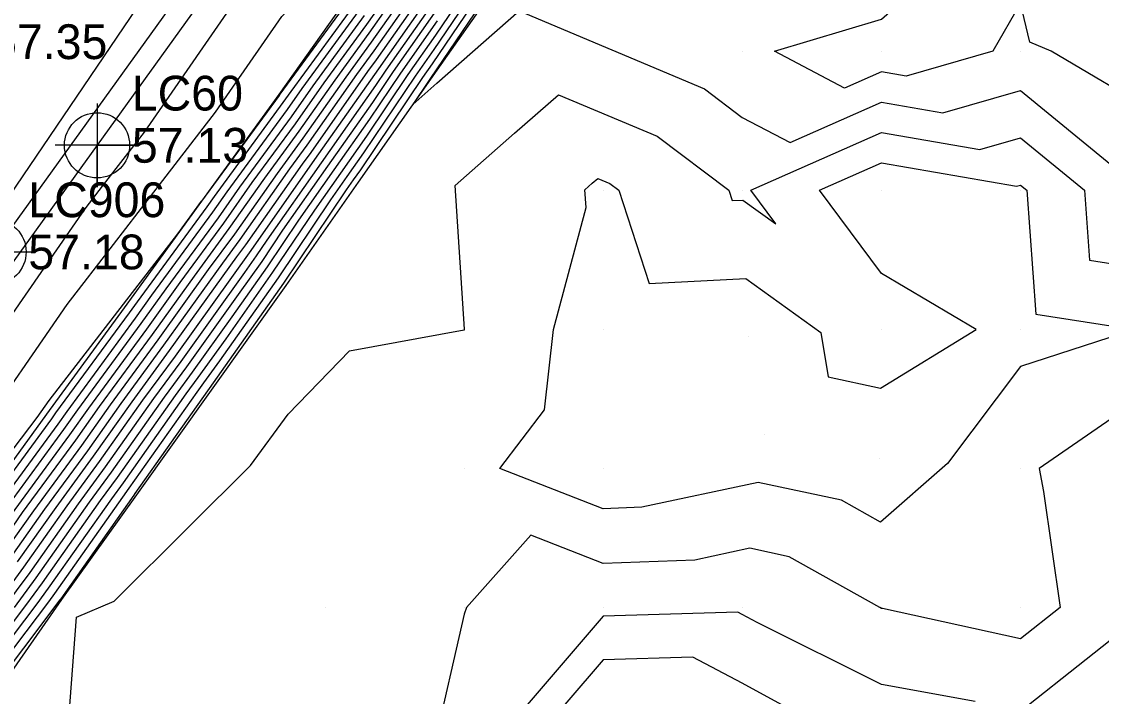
# Model space of a CAD drawing. Extents: x 2188792 to 2191981, y 386090 to 389710.
# Drawn here: x 2189698.4 to 2189776.1, y 386953.7 to 387002.3 of the extents above; entities that cross this region are included whole.
import ezdxf

# ---------------------------------------------------------------- set-up
doc = ezdxf.new("R2010")
doc.units = 0
for name, color, linetype in [('DTM Contours Major', 7, 'Continuous'), ('DTM Contours Minor', 7, 'Continuous'), ('Exist DTM QL2 LIDAR Elevation Point', 7, 'Continuous'), ('Exist Roads EOP', 7, 'Continuous'), ('Exist Roads EOP Cogo Elevation', 7, 'Continuous'), ('Exist Roads EOP Cogo Number', 7, 'Continuous'), ('Exist Roads EOP Cogo Point CELL', 7, 'Continuous'), ('Exist Roads EOT', 7, 'Continuous'), ('Exist Roads EOT Cogo Elevation', 7, 'Continuous'), ('Exist Roads EOT Cogo Number', 7, 'Continuous'), ('Exist Roads EOT Cogo Point CELL', 7, 'Continuous'), ('PH Exist DTM Breakline', 7, 'Continuous')]:
    doc.layers.add(name, color=color, linetype=linetype)

msp = doc.modelspace()

# ---------------------------------------------------------------- linework, layer by layer
at = {"layer": 'DTM Contours Major'}
for points in [[(2189690.321, 386970.473), (2189702.993, 386988.788), (2189704.322, 386990.511), (2189705.738, 386992.346), (2189707.249, 386994.304), (2189717.366, 387008.941), (2189718.756, 387010.444), (2189720.618, 387012.458), (2189723.242, 387015.296), (2189734.595, 387032.184), (2189736.495, 387033.703), (2189737.964, 387036.279), (2189739.21, 387038.462), (2189748.491, 387050.734), (2189750.059, 387053.337), (2189751.431, 387055.614), (2189750.977, 387056.76), (2189764.817, 387076.56)], [(2189731.016, 387005.466), (2189728.189, 387001.282), (2189726.193, 386998.439), (2189723.215, 386994.023), (2189721.346, 386991.363), (2189719.478, 386988.703), (2189716.473, 386984.23), (2189713.098, 386979.449), (2189711.094, 386976.657), (2189710.235, 386975.488), (2189705.717, 386969.084), (2189704.88, 386967.945), (2189700.342, 386961.512), (2189699.528, 386960.404), (2189694.991, 386954.414)], [(2189728.008, 387005.341), (2189723.907, 386999.502), (2189723.293, 386998.66), (2189719.209, 386992.844), (2189718.589, 386992), (2189714.51, 386986.192), (2189713.883, 386985.338), (2189709.045, 386978.598), (2189706.341, 386974.916), (2189703.581, 386971.003), (2189700.877, 386967.324), (2189698.116, 386963.409)], [(2189723.055, 387002.687), (2189719.368, 386997.637), (2189717.801, 386995.406), (2189714.085, 386990.343), (2189712.547, 386988.153), (2189708.788, 386983.034), (2189706.996, 386980.538), (2189702.447, 386974.345), (2189701.444, 386972.923), (2189696.874, 386966.702)]]:
    msp.add_lwpolyline(points, dxfattribs=at)
at = {"layer": 'DTM Contours Minor'}
for points in [[(2189809.4, 387152.406), (2189801.396, 387139.864), (2189794.846, 387131.758), (2189788.146, 387120.877), (2189781.876, 387111.472), (2189771.155, 387095.136), (2189767.896, 387090.241), (2189758.451, 387075.833), (2189755.214, 387070.994), (2189740.876, 387051.783), (2189738.057, 387047.608), (2189727.447, 387033.342), (2189723.289, 387027.488), (2189710.113, 387008.133), (2189707.688, 387004.715), (2189696.068, 386987.603)], [(2189694.937, 386972.126), (2189701.702, 386981.904), (2189705.036, 386986.223), (2189708.586, 386990.823), (2189712.374, 386995.732), (2189717.133, 387002.617), (2189721.107, 387006.915), (2189726.432, 387012.673), (2189732.935, 387019.706), (2189733.562, 387020.567), (2189733.582, 387020.591), (2189739.089, 387028.13), (2189739.289, 387028.377), (2189743.879, 387035.174), (2189744.039, 387035.369), (2189748.66, 387042.228), (2189748.771, 387042.362), (2189753.429, 387049.296), (2189753.48, 387049.355), (2189756.636, 387054.069), (2189757.992, 387056.32), (2189756.554, 387059.949)], [(2189770.901, 387000.78), (2189770.242, 387003.583), (2189768.255, 387000.121), (2189762.025, 386998.338), (2189760.241, 386998.646), (2189757.594, 386997.473), (2189752.556, 387000.121), (2189760.241, 387002.416), (2189769.018, 387010.122), (2189767.681, 387017.562), (2189767.664, 387020.123), (2189770.242, 387023.147), (2189772.595, 387022.475), (2189780.243, 387023.562)], [(2189731.604, 387005.483), (2189728.07, 387000.253), (2189726.722, 386998.332), (2189722.999, 386992.813), (2189721.81, 386991.121), (2189720.622, 386989.428), (2189716.865, 386983.838), (2189712.647, 386977.862), (2189711.504, 386976.269), (2189711.014, 386975.602), (2189706.144, 386968.701), (2189705.681, 386968.07), (2189700.788, 386961.133), (2189700.351, 386960.539), (2189695.456, 386954.076)], [(2189732.192, 387005.5), (2189727.951, 386999.224), (2189727.251, 386998.226), (2189722.783, 386991.602), (2189722.274, 386990.878), (2189721.766, 386990.154), (2189717.258, 386983.446), (2189712.195, 386976.274), (2189711.913, 386975.881), (2189711.792, 386975.716), (2189706.572, 386968.317), (2189706.482, 386968.194), (2189701.233, 386960.753), (2189701.174, 386960.674), (2189695.921, 386953.739)], [(2189728.665, 387005.397), (2189724.078, 386998.864), (2189719.49, 386992.332), (2189714.902, 386985.799), (2189709.455, 386978.209), (2189707.12, 386975.03), (2189704.008, 386970.62), (2189701.678, 386967.448), (2189698.562, 386963.03), (2189696.236, 386959.866)], [(2189726.035, 387005.172), (2189723.396, 387001.413), (2189720.938, 386998.046), (2189718.364, 386994.381), (2189715.887, 386991.006), (2189713.332, 386987.368), (2189710.826, 386983.956), (2189707.816, 386979.762), (2189704.005, 386974.573), (2189702.299, 386972.155), (2189698.475, 386966.951), (2189696.781, 386964.548)], [(2189726.693, 387005.228), (2189723.566, 387000.776), (2189721.723, 386998.251), (2189718.646, 386993.869), (2189716.787, 386991.337), (2189713.724, 386986.976), (2189711.845, 386984.417), (2189708.226, 386979.374), (2189704.784, 386974.688), (2189702.726, 386971.771), (2189699.276, 386967.075), (2189697.226, 386964.168)], [(2189727.35, 387005.284), (2189723.737, 387000.139), (2189722.508, 386998.455), (2189718.927, 386993.357), (2189717.688, 386991.669), (2189714.117, 386986.584), (2189712.864, 386984.878), (2189708.635, 386978.986), (2189705.562, 386974.802), (2189703.153, 386971.387), (2189700.077, 386967.199), (2189697.671, 386963.789)], [(2189725.378, 387005.115), (2189723.225, 387002.05), (2189720.153, 386997.842), (2189718.083, 386994.894), (2189714.986, 386990.675), (2189712.939, 386987.761), (2189709.807, 386983.495), (2189707.406, 386980.15), (2189703.226, 386974.459), (2189701.871, 386972.539), (2189697.675, 386966.826)], [(2189732.78, 387005.517), (2189727.833, 386998.195), (2189727.779, 386998.119), (2189726.547, 386996.292), (2189728.28, 386997.816), (2189734.197, 387003.02), (2189747.529, 386997.409), (2189750.24, 386995.358), (2189753.674, 386993.554), (2189760.241, 386996.463), (2189764.665, 386995.697), (2189770.242, 386997.294), (2189778.993, 386990.12)], [(2189694.035, 386966.557), (2189699.554, 386973.778), (2189700.412, 386975.019), (2189705.749, 386981.935), (2189709.658, 386987), (2189711.369, 386989.33), (2189711.382, 386989.349), (2189716.957, 386996.943), (2189717.013, 386997.024), (2189722.543, 387004.599)], [(2189728.546, 387004.368), (2189724.606, 386998.758), (2189723.862, 386997.654), (2189719.954, 386992.09), (2189716.046, 386986.525), (2189715.295, 386985.407), (2189714.451, 386984.212), (2189709.865, 386977.821), (2189707.899, 386975.145), (2189704.435, 386970.236), (2189702.479, 386967.572), (2189699.007, 386962.651), (2189697.059, 386960)], [(2189695.273, 386966.453), (2189700.59, 386973.69), (2189700.89, 386974.116), (2189706.177, 386981.314), (2189706.75, 386982.113), (2189711.761, 386988.937), (2189712.283, 386989.68), (2189717.239, 386996.431), (2189717.798, 386997.228), (2189722.714, 387003.962)], [(2189722.884, 387003.325), (2189718.583, 386997.433), (2189717.52, 386995.919), (2189713.184, 386990.012), (2189712.154, 386988.545), (2189707.769, 386982.573), (2189706.587, 386980.926), (2189701.669, 386974.23), (2189701.017, 386973.306), (2189696.074, 386966.577)], [(2189728.427, 387003.339), (2189725.135, 386998.652), (2189723.646, 386996.444), (2189720.418, 386991.847), (2189717.19, 386987.251), (2189715.688, 386985.015), (2189714, 386982.624), (2189710.274, 386977.433), (2189708.677, 386975.259), (2189704.862, 386969.852), (2189703.279, 386967.697), (2189699.452, 386962.271), (2189697.882, 386960.135)], [(2189728.308, 387002.31), (2189725.664, 386998.545), (2189723.43, 386995.233), (2189720.882, 386991.605), (2189718.334, 386987.977), (2189716.08, 386984.623), (2189713.549, 386981.037), (2189710.684, 386977.045), (2189709.456, 386975.373), (2189705.29, 386969.468), (2189704.08, 386967.821), (2189699.897, 386961.892), (2189698.705, 386960.27), (2189694.526, 386954.752)], [(2189780.243, 386995.53), (2189772.447, 387000.121), (2189770.901, 387000.78)], [(2189701.814, 386952.133), (2189702.366, 386959.444), (2189705.083, 386960.579), (2189710.475, 386965.953), (2189714.881, 386970.344), (2189717.599, 386974.034), (2189721.997, 386978.583), (2189730.239, 386980.079), (2189730.256, 386980.102), (2189730.258, 386980.119), (2189730.264, 386980.145), (2189729.598, 386990.469), (2189733.866, 386994.222), (2189737.019, 386996.995), (2189744.124, 386994.005), (2189749.26, 386990.12), (2189749.502, 386989.382), (2189750.269, 386989.421), (2189752.652, 386987.708), (2189750.851, 386990.12), (2189760.241, 386994.28), (2189767.305, 386993.057), (2189770.242, 386993.898), (2189774.851, 386990.12), (2189775.213, 386985.09), (2189780.243, 386984.303)], [(2189769.945, 386990.417), (2189770.242, 386990.502), (2189770.708, 386990.12), (2189771.349, 386981.226), (2189778.43, 386980.119), (2189770.242, 386977.45), (2189765.003, 386970.481), (2189760.169, 386966.263), (2189757.364, 386967.838), (2189751.386, 386969.118), (2189743.026, 386967.332), (2189740.24, 386967.231), (2189732.809, 386970.118), (2189736.013, 386974.344), (2189736.675, 386980.119), (2189739.007, 386988.887), (2189738.924, 386990.163), (2189739.452, 386990.627), (2189739.842, 386990.97), (2189740.72, 386990.6), (2189741.355, 386990.12), (2189743.548, 386983.427), (2189750.499, 386983.779), (2189755.896, 386979.9), (2189756.423, 386976.704), (2189760.184, 386975.898), (2189767.046, 386980.119), (2189760.241, 386984.144), (2189755.779, 386990.12), (2189760.241, 386992.097), (2189769.945, 386990.417)], [(2189780.243, 386976.086), (2189771.575, 386970.118), (2189771.885, 386968.475), (2189773.095, 386960.117), (2189770.242, 386957.867), (2189760.308, 386960.05), (2189760.241, 386960.062), (2189760.131, 386960.117), (2189753.617, 386963.776), (2189750.783, 386964.383), (2189746.821, 386963.537), (2189740.24, 386963.299), (2189735.037, 386965.32), (2189730.403, 386960.117), (2189730.239, 386959.659), (2189728.059, 386950.116)], [(2189787.04, 386950.231), (2189790.244, 386954.194), (2189792.088, 386958.273), (2189793.32, 386960.117), (2189790.244, 386963.795), (2189784.121, 386970.118), (2189780.243, 386971.78), (2189777.829, 386970.118), (2189779.596, 386960.765), (2189779.69, 386960.117), (2189770.242, 386952.663)], [(2189749.919, 386959.796), (2189740.24, 386959.516), (2189732.178, 386950.116)], [(2189766.978, 386953.381), (2189760.241, 386954.6), (2189751.317, 386959.041), (2189750.24, 386959.628), (2189749.919, 386959.796)], [(2189746.676, 386956.553), (2189740.24, 386956.366), (2189734.879, 386950.116), (2189736.874, 386943.481), (2189734.651, 386940.115), (2189740.24, 386935.153), (2189742.786, 386937.569), (2189750.24, 386938.206), (2189753.67, 386936.686), (2189753.681, 386940.115), (2189754.703, 386945.654), (2189758.62, 386950.116), (2189750.24, 386954.687), (2189746.676, 386956.553)]]:
    msp.add_lwpolyline(points, dxfattribs=at)
at = {"layer": 'Exist DTM QL2 LIDAR Elevation Point'}
for p, q in [((2189750.24, 387000.121), (2189750.24, 387000.121)), ((2189760.241, 387000.121), (2189760.241, 387000.121)), ((2189770.242, 387000.121), (2189770.242, 387000.121)), ((2189740.24, 386990.12), (2189740.24, 386990.12)), ((2189750.24, 386990.12), (2189750.24, 386990.12)), ((2189760.241, 386990.12), (2189760.241, 386990.12)), ((2189770.242, 386990.12), (2189770.242, 386990.12)), ((2189730.239, 386980.119), (2189730.239, 386980.119)), ((2189740.24, 386980.119), (2189740.24, 386980.119)), ((2189760.241, 386980.119), (2189760.241, 386980.119)), ((2189770.242, 386980.119), (2189770.242, 386980.119)), ((2189750.667, 386979.637), (2189750.667, 386979.637)), ((2189751.828, 386972.594), (2189751.828, 386972.594)), ((2189760.115, 386970.819), (2189760.115, 386970.819)), ((2189730.239, 386970.118), (2189730.239, 386970.118)), ((2189740.24, 386970.118), (2189740.24, 386970.118)), ((2189770.242, 386970.118), (2189770.242, 386970.118)), ((2189720.238, 386960.117), (2189720.238, 386960.117)), ((2189730.239, 386960.117), (2189730.239, 386960.117)), ((2189740.24, 386960.117), (2189740.24, 386960.117)), ((2189750.24, 386960.117), (2189750.24, 386960.117)), ((2189760.241, 386960.117), (2189760.241, 386960.117)), ((2189770.242, 386960.117), (2189770.242, 386960.117))]:
    msp.add_line(p, q, dxfattribs=at)
at = {"layer": 'Exist Roads EOP'}
msp.add_lwpolyline([(2190335.128, 387868.989), (2190306.373, 387829.271), (2190274.581, 387784.921), (2190245.133, 387744.071), (2190214.553, 387701.741), (2190184.89, 387660.475), (2190157.493, 387622.204), (2190126.048, 387578.501), (2190091.216, 387530.568), (2190059.634, 387486.726), (2190026.932, 387441.783), (2189997.689, 387401.032), (2189957.023, 387344.154), (2189927.908, 387303.922), (2189889.008, 387250.224), (2189856.606, 387205.5), (2189825.68, 387162.612), (2189795.668, 387120.822), (2189765.955, 387079.619), (2189734.998, 387036.704), (2189703.849, 386993.356), (2189673.984, 386951.979), (2189643.253, 386909.427)], dxfattribs=at)
at = {"layer": 'Exist Roads EOP Cogo Point CELL'}
msp.add_lwpolyline([(2189703.849, 386996.356), (2189703.849, 386990.356), (2189703.849, 386993.356), (2189706.849, 386993.356), (2189700.849, 386993.356)], dxfattribs=at)
msp.add_circle((2189703.849, 386993.356), 2.344, dxfattribs=at)
at = {"layer": 'Exist Roads EOT'}
msp.add_lwpolyline([(2189989.253, 387391.986), (2189958.581, 387349.453), (2189928.09, 387307.216), (2189909.67, 387281.603), (2189884.44, 387246.513), (2189852.91, 387202.766), (2189821.507, 387159.305), (2189790.01, 387115.85), (2189759.16, 387072.957), (2189728.247, 387029.91), (2189696.407, 386985.689), (2189665.45, 386942.736), (2189635.049, 386900.502)], dxfattribs=at)
at = {"layer": 'Exist Roads EOT Cogo Point CELL'}
msp.add_lwpolyline([(2189696.407, 386988.689), (2189696.407, 386982.689), (2189696.407, 386985.689), (2189693.407, 386985.689), (2189699.407, 386985.689)], dxfattribs=at)
msp.add_circle((2189696.407, 386985.689), 2.344, dxfattribs=at)
at = {"layer": 'PH Exist DTM Breakline'}
for points in [[(2189791.244, 387081.417), (2189785.633, 387076.29), (2189780.022, 387071.163), (2189774.864, 387065.758), (2189769.707, 387060.354), (2189764.723, 387053.993), (2189759.74, 387047.633), (2189754.442, 387040.492), (2189749.145, 387033.351), (2189743.848, 387026.211), (2189738.55, 387019.07), (2189733.253, 387011.929), (2189728.665, 387005.397), (2189724.078, 386998.864), (2189719.49, 386992.332), (2189714.902, 386985.799)], [(2189780.243, 387080.129), (2189775.664, 387077.506), (2189769.813, 387072.074), (2189764.002, 387064.208), (2189758.191, 387056.342), (2189753.421, 387049.372), (2189748.65, 387042.402), (2189743.88, 387035.432), (2189739.109, 387028.462), (2189733.563, 387020.597), (2189728.017, 387012.732), (2189722.471, 387004.866), (2189716.926, 386997.001), (2189711.359, 386989.34), (2189705.791, 386981.679), (2189700.224, 386974.018), (2189694.657, 386966.357)], [(2189733.024, 387005.524), (2189727.823, 386998.111), (2189722.622, 386990.697), (2189717.421, 386983.283), (2189712.048, 386975.754), (2189706.675, 386968.224), (2189701.302, 386960.695), (2189696.271, 386953.485), (2189691.241, 386946.275), (2189686.211, 386939.065), (2189681.181, 386931.855), (2189676.534, 386925.321), (2189671.888, 386918.787), (2189667.242, 386912.253), (2189662.596, 386905.719), (2189657.949, 386899.185), (2189653.071, 386892.669), (2189648.193, 386886.152), (2189643.315, 386879.636), (2189638.437, 386873.12), (2189633.559, 386866.603)]]:
    msp.add_lwpolyline(points, dxfattribs=at)

# ---------------------------------------------------------------- texts
at = {"layer": 'Exist Roads EOP Cogo Elevation'}
msp.add_text('57.13', height=2.5, dxfattribs=at).set_placement((2189706.349, 386992.106))
at = {"layer": 'Exist Roads EOP Cogo Number'}
msp.add_text('LC60', height=2.5, dxfattribs=at).set_placement((2189706.349, 386995.856))
at = {"layer": 'Exist Roads EOT Cogo Elevation'}
for s, p in [('57.35', (2189696.227, 386999.555)), ('57.18', (2189698.907, 386984.439))]:
    msp.add_text(s, height=2.5, dxfattribs=at).set_placement(p)
at = {"layer": 'Exist Roads EOT Cogo Number'}
msp.add_text('LC906', height=2.5, dxfattribs=at).set_placement((2189698.907, 386988.189))

doc.saveas('drawing.dxf')
